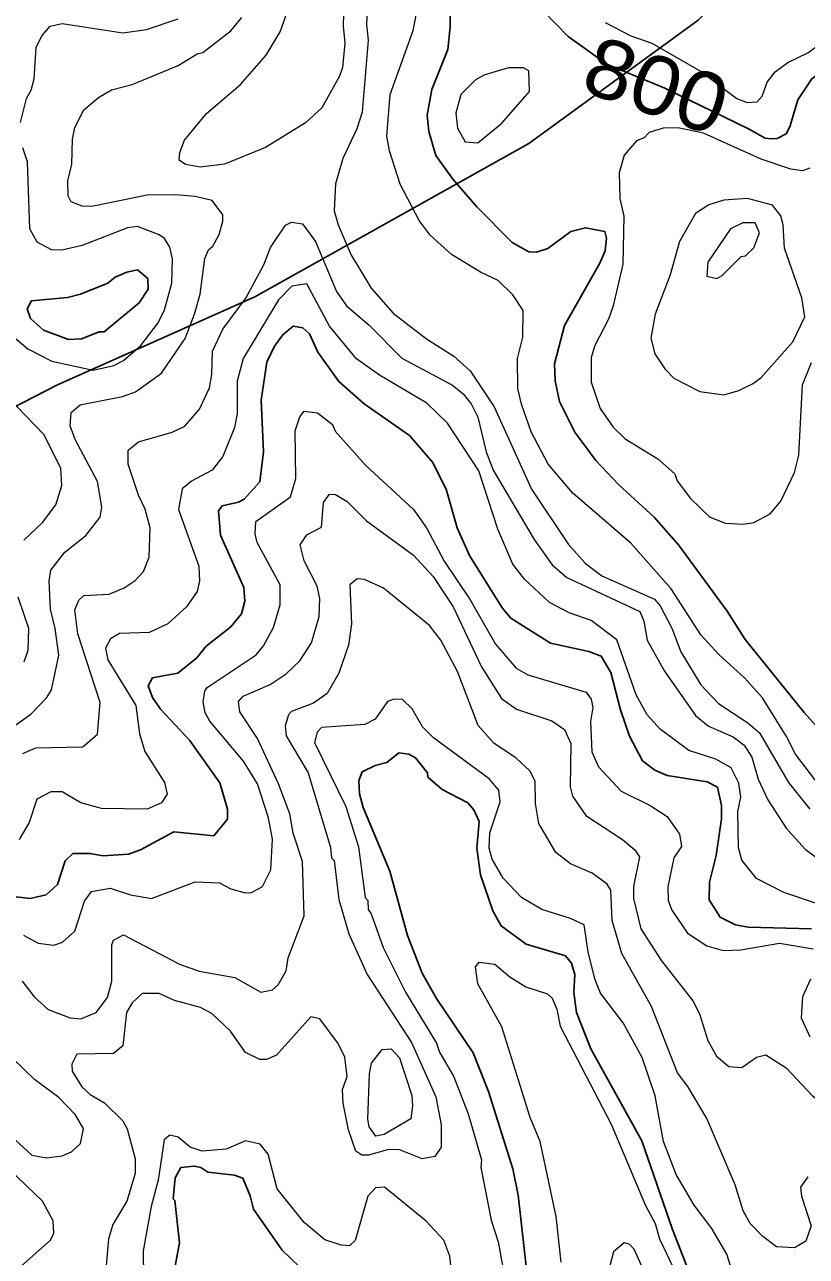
# Model space of a CAD drawing. Extents: x 673.3 to 698.5, y 6984.3 to 7012.3.
# Drawn here: x 677.472 to 678.535, y 6993.355 to 6995.03 of the extents above; entities that cross this region are included whole.
import ezdxf
from ezdxf.enums import TextEntityAlignment as Align

# ---------------------------------------------------------------- set-up
doc = ezdxf.new("R2010")
doc.units = 0
doc.header["$LTSCALE"] = 0.032
for name, color, linetype, lineweight in [('1', 7, 'Continuous', 25), ('2', 7, 'Continuous', 13), ('26', 7, 'Continuous', 25)]:
    doc.layers.add(name, color=color, linetype=linetype, lineweight=lineweight)
doc.layers.add('61', color=7, linetype='Continuous')

msp = doc.modelspace()

# ---------------------------------------------------------------- linework, layer by layer
at = {"layer": '1'}
for points in [[(678.5853, 6994.0351), (678.5319, 6994.0943), (678.452, 6994.1935), (678.4274, 6994.2323), (678.361, 6994.3224), (678.328, 6994.3601), (678.2794, 6994.4045), (678.2487, 6994.4368), (678.2201, 6994.4754), (678.1992, 6994.5173), (678.1932, 6994.5453), (678.1927, 6994.5685), (678.2061, 6994.6206), (678.2543, 6994.7053), (678.2612, 6994.7222), (678.2634, 6994.7395), (678.2608, 6994.7486), (678.2347, 6994.7536), (678.2147, 6994.7484), (678.1835, 6994.7252), (678.1681, 6994.7203), (678.1575, 6994.7206), (678.1347, 6994.7334), (678.0869, 6994.7819), (678.0542, 6994.8196), (678.031, 6994.8517), (678.0215, 6994.8843), (678.0191, 6994.9068), (678.0256, 6994.9415), (678.0476, 6994.9958), (678.0508, 6995.0268), (678.0495, 6995.0896)], [(678.1767, 6995.049), (678.2112, 6995.0134), (678.2636, 6994.9761), (678.3424, 6994.9432), (678.4562, 6994.888), (678.479, 6994.8752), (678.488, 6994.8742), (678.4955, 6994.8751), (678.5077, 6994.881), (678.5127, 6994.8908), (678.5233, 6994.9274), (678.5425, 6994.9562), (678.571, 6994.9772), (678.6016, 6994.9943), (678.6375, 6995.0195), (678.6437, 6995.0326)], [(678.542, 6993.8001), (678.4561, 6993.8026), (678.4385, 6993.8058), (678.4177, 6993.8159), (678.4027, 6993.8394), (678.4035, 6993.8638), (678.4125, 6993.8997), (678.4197, 6993.9496), (678.4197, 6993.9681), (678.4141, 6993.9927), (678.4002, 6994.0003), (678.3456, 6994.0086), (678.3291, 6994.016), (678.3124, 6994.0287), (678.2943, 6994.0622), (678.2822, 6994.0978), (678.2691, 6994.1486), (678.2561, 6994.1711), (678.2394, 6994.1772), (678.1872, 6994.1887), (678.1332, 6994.2226), (678.1212, 6994.2365), (678.0769, 6994.308), (678.0599, 6994.3456), (678.045, 6994.3981), (678.0264, 6994.4348), (677.9954, 6994.471), (677.9335, 6994.5142), (677.8991, 6994.5446), (677.8705, 6994.5844), (677.8595, 6994.6093), (677.8501, 6994.6176), (677.8372, 6994.6198), (677.823, 6994.6081), (677.8116, 6994.5927), (677.8013, 6994.5707), (677.7936, 6994.5191), (677.7967, 6994.4486), (677.7916, 6994.4081), (677.7705, 6994.3846), (677.7629, 6994.3803), (677.7403, 6994.3752), (677.7355, 6994.3688), (677.7382, 6994.3354), (677.7698, 6994.2642), (677.7715, 6994.2458), (677.7667, 6994.2287), (677.7523, 6994.211), (677.7188, 6994.1846), (677.7061, 6994.1687), (677.6803, 6994.148), (677.6458, 6994.1413), (677.6398, 6994.1306), (677.6459, 6994.1147), (677.6566, 6994.099), (677.6963, 6994.0568), (677.7373, 6993.9987), (677.7478, 6993.9629), (677.7478, 6993.9494), (677.729, 6993.9267), (677.6749, 6993.9319), (677.6293, 6993.9077), (677.613, 6993.9019), (677.5782, 6993.8995), (677.5609, 6993.9026), (677.5372, 6993.9026)], [(678.4153, 6993.2322), (678.3528, 6993.3915), (678.3113, 6993.512), (678.2417, 6993.6368), (678.2226, 6993.6863), (678.2187, 6993.7136), (678.2202, 6993.7381), (678.2154, 6993.7533), (678.2073, 6993.7635), (678.1539, 6993.7795), (678.1201, 6993.8042), (678.1085, 6993.8247), (678.0918, 6993.8736), (678.0867, 6993.9101), (678.0899, 6993.9463), (678.0826, 6993.962), (678.0746, 6993.9716), (678.0397, 6993.9897), (678.0203, 6994.0065), (678.0197, 6994.0125), (678.0036, 6994.0329), (677.9946, 6994.0378), (677.9809, 6994.0393), (677.9645, 6994.0265), (677.9485, 6994.0224), (677.9311, 6994.0139), (677.9263, 6994.002), (677.9271, 6993.9838)], [(677.9271, 6993.9838), (677.9322, 6993.9654), (677.9685, 6993.8785), (677.9925, 6993.7912), (678.0124, 6993.74), (678.0321, 6993.7055), (678.0821, 6993.6316), (678.1028, 6993.5788), (678.136, 6993.474), (678.1429, 6993.4381), (678.1591, 6993.297)], [(677.5372, 6993.9026), (677.5272, 6993.8928), (677.5166, 6993.8604), (677.5011, 6993.8465), (677.4794, 6993.8416), (677.4528, 6993.8444)], [(677.8579, 6993.3288), (677.8219, 6993.3631), (677.783, 6993.419), (677.7787, 6993.4371), (677.7687, 6993.4612), (677.7574, 6993.4652), (677.721, 6993.4693), (677.7115, 6993.4757), (677.7026, 6993.4775), (677.6844, 6993.4758), (677.6764, 6993.4615), (677.6738, 6993.4331), (677.6762, 6993.4308), (677.6827, 6993.373), (677.6698, 6993.3052)]]:
    msp.add_lwpolyline(points, dxfattribs=at)
msp.add_lwpolyline([(677.5848, 6994.6783), (677.5951, 6994.6862), (677.6108, 6994.6933), (677.6254, 6994.6965), (677.6396, 6994.6845), (677.64, 6994.6701), (677.6277, 6994.6514), (677.5801, 6994.6121), (677.573, 6994.6119), (677.5492, 6994.6023), (677.5313, 6994.6014), (677.4974, 6994.6143), (677.4799, 6994.6302), (677.4752, 6994.6432), (677.4811, 6994.6543), (677.53, 6994.6585), (677.5478, 6994.6634)], close=True, dxfattribs=at)
at = {"layer": '2'}
for points in [[(677.9067, 6995.092), (677.905, 6995.0275), (677.9074, 6995.0046), (677.9043, 6994.9715), (677.9003, 6994.9597), (677.876, 6994.9168), (677.854, 6994.8964), (677.7995, 6994.8626), (677.7439, 6994.8398), (677.7108, 6994.836), (677.6907, 6994.8393), (677.682, 6994.8452), (677.6828, 6994.8558), (677.6892, 6994.8724), (677.7191, 6994.909), (677.7655, 6994.9482), (677.8004, 6994.9884), (677.8195, 6995.02), (677.8317, 6995.0542)], [(677.9385, 6995.0724), (677.9368, 6995.0297), (677.9392, 6995.0084), (677.9311, 6994.9109), (677.9237, 6994.888), (677.9044, 6994.8476), (677.8945, 6994.8134), (677.8929, 6994.7767), (677.8984, 6994.7577), (677.9155, 6994.7173), (677.9433, 6994.6714)], [(678.5481, 6994.0015), (678.5201, 6994.0376), (678.5079, 6994.0617), (678.4752, 6994.1145), (678.451, 6994.1416), (678.4161, 6994.1734), (678.3913, 6994.1999), (678.3513, 6994.2626), (678.2965, 6994.3247), (678.2173, 6994.3926), (678.184, 6994.4322), (678.1608, 6994.4758), (678.1474, 6994.5138), (678.1428, 6994.5349), (678.1421, 6994.5756), (678.1494, 6994.6049), (678.1501, 6994.641), (678.1357, 6994.6622), (678.1159, 6994.682), (678.0918, 6994.6932), (678.0522, 6994.7172), (678.0233, 6994.7436), (678.0083, 6994.7632), (677.9827, 6994.8126), (677.9679, 6994.8581), (677.9645, 6994.878), (677.9692, 6994.9347), (678.0003, 6995.0216), (678.0068, 6995.054)], [(677.4664, 6994.8966), (677.4743, 6994.9292), (677.4807, 6994.9404), (677.4848, 6994.9562), (677.4876, 6994.9986), (677.4951, 6995.0146), (677.5066, 6995.0278), (677.5231, 6995.0313), (677.6055, 6995.0184), (677.6378, 6995.023), (677.6805, 6995.0374)], [(677.6582, 6994.5557), (677.69, 6994.603), (677.7031, 6994.6359), (677.7104, 6994.6633), (677.7169, 6994.7118), (677.7218, 6994.7233), (677.7277, 6994.7287), (677.7363, 6994.7445), (677.7413, 6994.7624), (677.7412, 6994.771), (677.727, 6994.7907), (677.7037, 6994.7961), (677.6775, 6994.7985), (677.6387, 6994.7976), (677.5632, 6994.7822), (677.55, 6994.783), (677.535, 6994.7888), (677.5312, 6994.7971), (677.5305, 6994.8172), (677.5362, 6994.8398), (677.537, 6994.874), (677.5403, 6994.89), (677.5523, 6994.9139), (677.5725, 6994.9307), (677.5899, 6994.9409), (677.6182, 6994.9485), (677.6806, 6994.974), (677.7063, 6994.9898), (677.7142, 6994.9918), (677.7525, 6995.0215), (677.7672, 6995.0393)], [(678.2613, 6995.0325), (678.2963, 6995.0145), (678.3247, 6995.0043), (678.3909, 6994.9664), (678.4403, 6994.9293), (678.4547, 6994.9239), (678.468, 6994.9249), (678.4749, 6994.9324), (678.4818, 6994.9517), (678.4924, 6994.9656), (678.5099, 6994.9783), (678.5371, 6994.9912), (678.5543, 6995.004), (678.5581, 6995.0095), (678.5585, 6995.0188), (678.5474, 6995.0305)], [(678.5396, 6994.8344), (678.5297, 6994.8311), (678.514, 6994.8333), (678.4736, 6994.8469), (678.3951, 6994.8821), (678.3603, 6994.8896), (678.3405, 6994.8888), (678.3212, 6994.8831), (678.3145, 6994.8759), (678.3039, 6994.8715), (678.2872, 6994.8524), (678.2805, 6994.8284), (678.2813, 6994.7934), (678.2869, 6994.7691), (678.2853, 6994.7038), (678.2724, 6994.6473), (678.2658, 6994.6291), (678.2472, 6994.5935), (678.2422, 6994.5772), (678.2422, 6994.5436), (678.2545, 6994.5077), (678.2723, 6994.4824), (678.2884, 6994.4663), (678.3329, 6994.4392), (678.3561, 6994.4188), (678.3594, 6994.4096), (678.3775, 6994.3853), (678.4032, 6994.3605), (678.4248, 6994.352), (678.4492, 6994.3506), (678.4636, 6994.3527), (678.4856, 6994.3646), (678.5005, 6994.3818), (678.519, 6994.4206), (678.5246, 6994.4445), (678.5297, 6994.5398), (678.5421, 6994.5705)], [(677.6548, 6994.7439), (677.6255, 6994.7552), (677.6118, 6994.7536), (677.5502, 6994.7296), (677.5225, 6994.7229), (677.5083, 6994.7237), (677.4887, 6994.7337), (677.479, 6994.7522), (677.4757, 6994.8431), (677.4694, 6994.8621)], [(677.4696, 6994.0384), (677.4871, 6994.0461), (677.5508, 6994.0478), (677.5711, 6994.0651), (677.5744, 6994.1078), (677.5441, 6994.2014), (677.5403, 6994.2341), (677.5454, 6994.2471), (677.5523, 6994.2535), (677.5866, 6994.2553), (677.6071, 6994.2638), (677.6224, 6994.274), (677.6333, 6994.286), (677.6412, 6994.3055), (677.6428, 6994.3456), (677.636, 6994.3708), (677.6265, 6994.3899), (677.6127, 6994.432), (677.6127, 6994.4513), (677.6265, 6994.4624), (677.6723, 6994.4755), (677.6898, 6994.4835), (677.7097, 6994.5068), (677.7233, 6994.5358), (677.7266, 6994.5541), (677.7272, 6994.5855), (677.7412, 6994.6158), (677.7725, 6994.6578), (677.797, 6994.7029), (677.8064, 6994.7266), (677.8265, 6994.7571), (677.8347, 6994.7611), (677.8497, 6994.7587), (677.8675, 6994.7349), (677.8959, 6994.6668), (677.9094, 6994.6475), (677.9406, 6994.6211), (677.9848, 6994.5763), (678.0538, 6994.5393), (678.0681, 6994.5278), (678.079, 6994.5139), (678.0881, 6994.4958), (678.0995, 6994.449), (678.1093, 6994.4241), (678.165, 6994.3297), (678.1892, 6994.2952), (678.2093, 6994.2781), (678.3086, 6994.2317), (678.314, 6994.2187), (678.3185, 6994.1927), (678.3422, 6994.1505), (678.3843, 6994.0904), (678.4018, 6994.0759), (678.4355, 6994.0613), (678.4505, 6994.05), (678.4609, 6994.0336), (678.4693, 6994.0039)], [(677.4179, 6994.6379), (677.4761, 6994.5888), (677.5088, 6994.5722), (677.5651, 6994.5599), (677.5931, 6994.5663), (677.6065, 6994.5731), (677.63, 6994.5935), (677.6533, 6994.624), (677.6623, 6994.6421), (677.6722, 6994.6782), (677.6729, 6994.7111), (677.6695, 6994.7271), (677.6623, 6994.7388), (677.6548, 6994.7439)], [(677.8556, 6994.6772), (677.8353, 6994.6739), (677.8173, 6994.6556), (677.7692, 6994.5756), (677.7609, 6994.5451), (677.7608, 6994.5004), (677.7575, 6994.4819), (677.7415, 6994.4424), (677.7268, 6994.424), (677.699, 6994.4091), (677.686, 6994.3986), (677.6811, 6994.3702), (677.7087, 6994.2935), (677.7095, 6994.2734), (677.7063, 6994.2588), (677.6922, 6994.2379), (677.6667, 6994.215), (677.6411, 6994.2033), (677.6007, 6994.2016), (677.5887, 6994.1946), (677.5818, 6994.1819), (677.585, 6994.1659), (677.623, 6994.1037), (677.6282, 6994.0652), (677.6354, 6994.0414), (677.6619, 6993.9994), (677.6655, 6993.9833), (677.6579, 6993.9717), (677.6383, 6993.963), (677.5765, 6993.9638), (677.5482, 6993.9716), (677.5231, 6993.9865), (677.5075, 6993.9866), (677.4885, 6993.9766), (677.4782, 6993.9448), (677.4645, 6993.9215)], [(678.6056, 6993.8157), (678.5043, 6993.8494), (678.467, 6993.8685), (678.4473, 6993.8936), (678.4426, 6993.9105), (678.4418, 6993.9599), (678.4457, 6993.9792), (678.443, 6993.9982), (678.4327, 6994.0189), (678.4118, 6994.0307), (678.3752, 6994.0426), (678.3363, 6994.0716), (678.3186, 6994.0912), (678.3035, 6994.1186), (678.2771, 6994.1933), (678.2422, 6994.2194), (678.2124, 6994.2299), (678.1857, 6994.244), (678.1517, 6994.2755), (678.1359, 6994.2962), (678.1153, 6994.3438), (678.0898, 6994.423), (678.0471, 6994.488), (678.0189, 6994.5149), (677.9544, 6994.5532), (677.9232, 6994.5751), (677.8866, 6994.6197), (677.8556, 6994.6772)], [(677.9433, 6994.6714), (677.9732, 6994.6375), (678.0185, 6994.6025), (678.0555, 6994.5787), (678.0778, 6994.5588), (678.1104, 6994.51), (678.1611, 6994.3982), (678.2116, 6994.3226), (678.2343, 6994.2974), (678.2568, 6994.2804), (678.3286, 6994.2484), (678.3363, 6994.2393), (678.352, 6994.2091), (678.3641, 6994.1769), (678.3914, 6994.1321), (678.4154, 6994.1066), (678.4553, 6994.0805), (678.4715, 6994.0667), (678.5106, 6993.9994), (678.5396, 6993.9627)], [(677.4706, 6994.3289), (677.496, 6994.3529), (677.5141, 6994.3766), (677.5223, 6994.403), (677.5213, 6994.4265), (677.498, 6994.4725), (677.4124, 6994.5606)], [(677.4167, 6994.0472), (677.4805, 6994.0922), (677.5021, 6994.1146), (677.5086, 6994.1251), (677.5182, 6994.1724), (677.5134, 6994.2086), (677.5069, 6994.235), (677.5051, 6994.2736), (677.5075, 6994.2879), (677.5265, 6994.3125), (677.5549, 6994.3352), (677.5744, 6994.3599), (677.5768, 6994.3734), (677.5708, 6994.4084), (677.5406, 6994.4654), (677.5339, 6994.484), (677.5352, 6994.5023), (677.5473, 6994.5127), (677.6048, 6994.5241), (677.6227, 6994.5306), (677.6582, 6994.5557)], [(677.8195, 6994.268), (677.788, 6994.3255), (677.7854, 6994.3372), (677.7862, 6994.3543), (677.8333, 6994.3876), (677.8409, 6994.4126), (677.8398, 6994.4773), (677.8462, 6994.4965), (677.8522, 6994.5041), (677.87, 6994.502), (677.8907, 6994.4861), (677.8942, 6994.4769), (677.9355, 6994.4309), (678.0009, 6994.3704), (678.0182, 6994.3456), (678.0426, 6994.3), (678.0778, 6994.2475), (678.1121, 6994.1875), (678.1402, 6994.1546), (678.1562, 6994.1457), (678.2354, 6994.1218), (678.2425, 6994.1126), (678.2447, 6994.1013), (678.2413, 6994.0823), (678.2431, 6994.0411), (678.2522, 6994.0206), (678.2832, 6993.9873), (678.3228, 6993.9677), (678.3456, 6993.9531), (678.3627, 6993.9287), (678.3651, 6993.912), (678.355, 6993.8969), (678.3465, 6993.8573), (678.3473, 6993.8385), (678.3519, 6993.8257), (678.3733, 6993.7944), (678.3999, 6993.777), (678.4219, 6993.7708), (678.4457, 6993.7716), (678.4987, 6993.7805), (678.5443, 6993.7731)], [(677.4686, 6993.7291), (677.485, 6993.7079), (677.5038, 6993.6907), (677.534, 6993.6792), (677.5483, 6993.6779), (677.5692, 6993.6864), (677.5847, 6993.7069), (677.5906, 6993.7289), (677.5906, 6993.7785), (677.5929, 6993.785), (677.6065, 6993.7919), (677.6824, 6993.752), (677.7092, 6993.7425), (677.7577, 6993.7339), (677.7929, 6993.7139), (677.8089, 6993.7173), (677.8166, 6993.724), (677.8276, 6993.7431), (677.8301, 6993.7606), (677.8521, 6993.8179), (677.8496, 6993.8918), (677.837, 6993.9303), (677.8325, 6993.9564), (677.8169, 6993.9974), (677.7885, 6994.059), (677.7647, 6994.0952), (677.7626, 6994.1092), (677.7689, 6994.1164), (677.806, 6994.1324), (677.8277, 6994.147), (677.846, 6994.1645), (677.8618, 6994.1893), (677.8724, 6994.2251), (677.8732, 6994.2496), (677.8698, 6994.2661), (677.8519, 6994.3007), (677.8465, 6994.3223), (677.8556, 6994.3359), (677.8755, 6994.3464), (677.8783, 6994.3801), (677.8867, 6994.3912), (677.8946, 6994.391), (677.9107, 6994.3814), (677.9368, 6994.3548), (678.0009, 6994.3083), (678.0277, 6994.2792), (678.0548, 6994.2381), (678.0932, 6994.1565), (678.1204, 6994.1132), (678.1407, 6994.0988), (678.1887, 6994.0829), (678.2059, 6994.0714), (678.2146, 6994.0522), (678.2136, 6993.9933), (678.2171, 6993.9806), (678.2353, 6993.9543), (678.2852, 6993.9215), (678.3016, 6993.9075), (678.3079, 6993.898), (678.3001, 6993.8576), (678.3, 6993.8415), (678.3101, 6993.8), (678.3381, 6993.7565), (678.3806, 6993.7023), (678.3895, 6993.6847), (678.4012, 6993.6483), (678.4128, 6993.6269), (678.4298, 6993.6128), (678.4472, 6993.6117), (678.467, 6993.6257), (678.48, 6993.6289)], [(677.4704, 6993.7915), (677.4903, 6993.7806), (677.5117, 6993.7781), (677.5232, 6993.7822), (677.5401, 6993.797), (677.5534, 6993.8378), (677.5629, 6993.8511), (677.5882, 6993.8553), (677.6159, 6993.8464), (677.6444, 6993.8416), (677.7039, 6993.8643), (677.7368, 6993.8628), (677.7521, 6993.8548), (677.7717, 6993.849), (677.7803, 6993.8495), (677.7954, 6993.8577), (677.8066, 6993.8802), (677.8089, 6993.9222), (677.8033, 6993.9512), (677.7884, 6993.9974), (677.7696, 6994.0283), (677.7239, 6994.0824), (677.7175, 6994.0939), (677.7145, 6994.1088), (677.7168, 6994.1235), (677.7201, 6994.1282), (677.7868, 6994.1728), (677.7967, 6994.1848), (677.8101, 6994.2099), (677.8194, 6994.2407), (677.8195, 6994.268)], [(678.5371, 6993.4628), (678.5272, 6993.4491), (678.5285, 6993.4367), (678.5418, 6993.3962), (678.5342, 6993.3756), (678.5189, 6993.3662), (678.4946, 6993.3678), (678.4757, 6993.3817), (678.4587, 6993.3996), (678.4493, 6993.4166), (678.4382, 6993.4522), (678.3996, 6993.5421), (678.3739, 6993.5856), (678.3596, 6993.6044), (678.3243, 6993.6944), (678.284, 6993.7668), (678.2708, 6993.8115), (678.269, 6993.8526), (678.2642, 6993.8608), (678.2438, 6993.8757), (678.2143, 6993.8885), (678.1941, 6993.9038), (678.1713, 6993.9436), (678.1665, 6993.9704), (678.1664, 6994.0009), (678.1591, 6994.015), (678.1404, 6994.0321), (678.1102, 6994.0528), (678.0885, 6994.0769), (678.0605, 6994.1502), (678.0377, 6994.1925), (678.0224, 6994.2127), (677.9601, 6994.2636), (677.9342, 6994.2754), (677.924, 6994.2763), (677.9141, 6994.268), (677.9164, 6994.215), (677.9123, 6994.186), (677.899, 6994.148), (677.8831, 6994.1202), (677.8649, 6994.107), (677.8346, 6994.0956), (677.8306, 6994.0912), (677.8261, 6994.0762), (677.8277, 6994.0625), (677.8575, 6994.0124), (677.8879, 6993.9108), (677.8894, 6993.8967), (677.8928, 6993.8933), (677.8991, 6993.8402), (677.9126, 6993.7933), (677.9376, 6993.7381), (677.9982, 6993.6455), (678.0313, 6993.5717), (678.0385, 6993.5336), (678.0385, 6993.5035), (678.0296, 6993.4907), (678.0124, 6993.4874), (677.9808, 6993.5003), (677.9652, 6993.4996), (677.9395, 6993.4922), (677.9303, 6993.4923), (677.9221, 6993.498), (677.9122, 6993.527), (677.9049, 6993.5633), (677.9043, 6993.5815), (677.9106, 6993.5994), (677.9074, 6993.6257), (677.8982, 6993.6442), (677.8734, 6993.6776), (677.8611, 6993.6805), (677.8143, 6993.6282), (677.8006, 6993.6226), (677.7918, 6993.6225), (677.7724, 6993.6321), (677.7517, 6993.6609), (677.7266, 6993.6852), (677.7112, 6993.6933), (677.6756, 6993.7029), (677.6547, 6993.7121), (677.6319, 6993.7121), (677.6182, 6993.6996), (677.6104, 6993.6863), (677.6054, 6993.6411), (677.5928, 6993.6307), (677.543, 6993.6298), (677.5362, 6993.616), (677.5367, 6993.6066), (677.5497, 6993.5853), (677.561, 6993.5748), (677.5804, 6993.5636), (677.6055, 6993.5392), (677.6115, 6993.5281), (677.6224, 6993.4873), (677.6224, 6993.4674), (677.6107, 6993.4297), (677.5918, 6993.3983), (677.5859, 6993.3785), (677.5809, 6993.3207)], [(677.471, 6994.1632), (677.4765, 6994.179), (677.4774, 6994.2088), (677.4629, 6994.251)], [(678.4491, 6993.287), (678.4267, 6993.3576), (678.4067, 6993.3928), (678.3824, 6993.4243), (678.358, 6993.4662), (678.3409, 6993.5111), (678.3294, 6993.5733), (678.3117, 6993.6251), (678.2857, 6993.6724), (678.255, 6993.7128), (678.2476, 6993.7307), (678.2383, 6993.7685), (678.233, 6993.8057), (678.2143, 6993.8144), (678.1753, 6993.8266), (678.1475, 6993.8426), (678.1226, 6993.8692), (678.1077, 6993.8948), (678.1038, 6993.9098), (678.1047, 6993.9309), (678.1184, 6993.9727), (678.1167, 6993.9886), (678.1037, 6994.0043), (678.028, 6994.0598), (678.0128, 6994.075), (677.9988, 6994.0995), (677.9856, 6994.1121), (677.9745, 6994.1127), (677.9655, 6994.1093), (677.9484, 6994.0853), (677.9345, 6994.0781), (677.8756, 6994.0738), (677.8699, 6994.0677), (677.866, 6994.0536), (677.9089, 6993.9667), (677.9261, 6993.9115), (677.9352, 6993.8427), (677.9384, 6993.8388), (677.9389, 6993.8265), (677.9433, 6993.8205), (677.9594, 6993.7747), (677.9897, 6993.7139), (678.032, 6993.6445), (678.0362, 6993.6324), (678.0556, 6993.5991), (678.0749, 6993.5487), (678.093, 6993.486), (678.0924, 6993.4756), (678.1062, 6993.4039), (678.116, 6993.3746), (678.124, 6993.3299)], [(678.4693, 6994.0039), (678.4826, 6993.9758), (678.5075, 6993.9371), (678.5333, 6993.9087), (678.5544, 6993.8931)], [(678.2015, 6993.3469), (678.1949, 6993.4091), (678.1731, 6993.5111), (678.1594, 6993.5437), (678.1207, 6993.6668), (678.0881, 6993.7254), (678.0851, 6993.7484), (678.0899, 6993.7549), (678.1115, 6993.752), (678.1316, 6993.7349), (678.1537, 6993.7211), (678.1831, 6993.7119), (678.1894, 6993.706), (678.1957, 6993.6909), (678.2, 6993.6679), (678.2697, 6993.5348), (678.3163, 6993.4238), (678.3292, 6993.3996), (678.3354, 6993.3788), (678.3569, 6993.3329)], [(678.5406, 6993.7317), (678.53, 6993.7079), (678.5281, 6993.679), (678.5396, 6993.6535)], [(678.48, 6993.6289), (678.5075, 6993.6112), (678.5433, 6993.573), (678.5739, 6993.549), (678.5969, 6993.5423), (678.6342, 6993.5402), (678.6564, 6993.5338), (678.6615, 6993.5189), (678.6651, 6993.4928), (678.6752, 6993.4651), (678.6978, 6993.4352), (678.7214, 6993.415), (678.8463, 6993.3614), (678.8924, 6993.3447)], [(677.4591, 6993.5131), (677.4818, 6993.4926), (677.5016, 6993.489), (677.5229, 6993.4917), (677.5356, 6993.4968), (677.5479, 6993.5084), (677.5521, 6993.5285), (677.5408, 6993.5479), (677.5185, 6993.571), (677.4851, 6993.5952), (677.4559, 6993.624)], [(677.7461, 6993.5005), (677.7131, 6993.4977), (677.6971, 6993.5032), (677.6806, 6993.5169), (677.6693, 6993.5198), (677.6615, 6993.5131), (677.6535, 6993.4584), (677.6438, 6993.4227), (677.6329, 6993.3624), (677.6339, 6993.2932)], [(678.0549, 6993.3143), (678.0501, 6993.3551), (678.0418, 6993.377), (678.018, 6993.4028), (677.9611, 6993.4489), (677.9491, 6993.4481), (677.9386, 6993.4367), (677.9213, 6993.3766), (677.9136, 6993.3693), (677.9023, 6993.3701), (677.88, 6993.3774), (677.8522, 6993.4009), (677.8154, 6993.4468), (677.8032, 6993.4938), (677.7921, 6993.5073), (677.7724, 6993.5117), (677.7461, 6993.5005)], [(677.4555, 6993.331), (677.5072, 6993.377), (677.5116, 6993.3862), (677.5106, 6993.4033), (677.4961, 6993.4297), (677.4519, 6993.4723)], [(678.3122, 6993.3393), (678.3007, 6993.3645), (678.2941, 6993.3716), (678.2873, 6993.3731), (678.2728, 6993.3609), (678.2618, 6993.3195)]]:
    msp.add_lwpolyline(points, dxfattribs=at)
for points in [[(678.121, 6994.8958), (678.1583, 6994.9388), (678.1574, 6994.9669), (678.1502, 6994.971), (678.13, 6994.971), (678.0962, 6994.9612), (678.0845, 6994.9544), (678.0651, 6994.9346), (678.0582, 6994.9095), (678.0606, 6994.8889), (678.0711, 6994.8704), (678.0881, 6994.8688)], [(678.4226, 6994.5265), (678.443, 6994.532), (678.462, 6994.5413), (678.4735, 6994.55), (678.5168, 6994.5984), (678.533, 6994.6325), (678.5288, 6994.6583), (678.5055, 6994.7257), (678.5036, 6994.7577), (678.5003, 6994.7697), (678.489, 6994.7844), (678.455, 6994.7935), (678.4228, 6994.7912), (678.4026, 6994.7846), (678.3844, 6994.7728), (678.3626, 6994.735), (678.3497, 6994.6896), (678.3294, 6994.6359), (678.3237, 6994.6033), (678.3291, 6994.5822), (678.3424, 6994.5615), (678.3549, 6994.5488), (678.3903, 6994.5309)], [(678.4207, 6994.6886), (678.4464, 6994.7142), (678.4524, 6994.7155), (678.4636, 6994.726), (678.4711, 6994.7468), (678.4652, 6994.7601), (678.4486, 6994.7602), (678.432, 6994.752), (678.4012, 6994.7066), (678.3997, 6994.6875), (678.4132, 6994.6845)], [(677.9409, 6993.6032), (677.9434, 6993.6176), (677.9582, 6993.6363), (677.9702, 6993.637), (677.9817, 6993.6246), (677.9986, 6993.5736), (677.9995, 6993.5594), (677.9969, 6993.542), (677.9607, 6993.5205), (677.9497, 6993.5184), (677.9404, 6993.5308), (677.9387, 6993.5415)]]:
    msp.add_lwpolyline(points, close=True, dxfattribs=at)
at = {"layer": '26'}
msp.add_lwpolyline([(677.3742, 6994.467), (677.5164, 6994.5397), (677.7848, 6994.6597), (678.1576, 6994.8682), (678.3881, 6995.0356), (678.565, 6995.2124), (678.7198, 6995.4557), (678.8209, 6995.6357), (678.9567, 6995.8726), (679.0717, 6996.0216), (679.1759, 6996.1407), (679.3397, 6996.2995), (679.4787, 6996.4235), (679.6027, 6996.5178)], dxfattribs=at)

# ---------------------------------------------------------------- texts
at = {"layer": '61', "width": 1.1}
msp.add_text('800', height=0.08, rotation=341.288, dxfattribs=at).set_placement((678.3181, 6994.9092), align=Align.CENTER)

doc.saveas('drawing.dxf')
